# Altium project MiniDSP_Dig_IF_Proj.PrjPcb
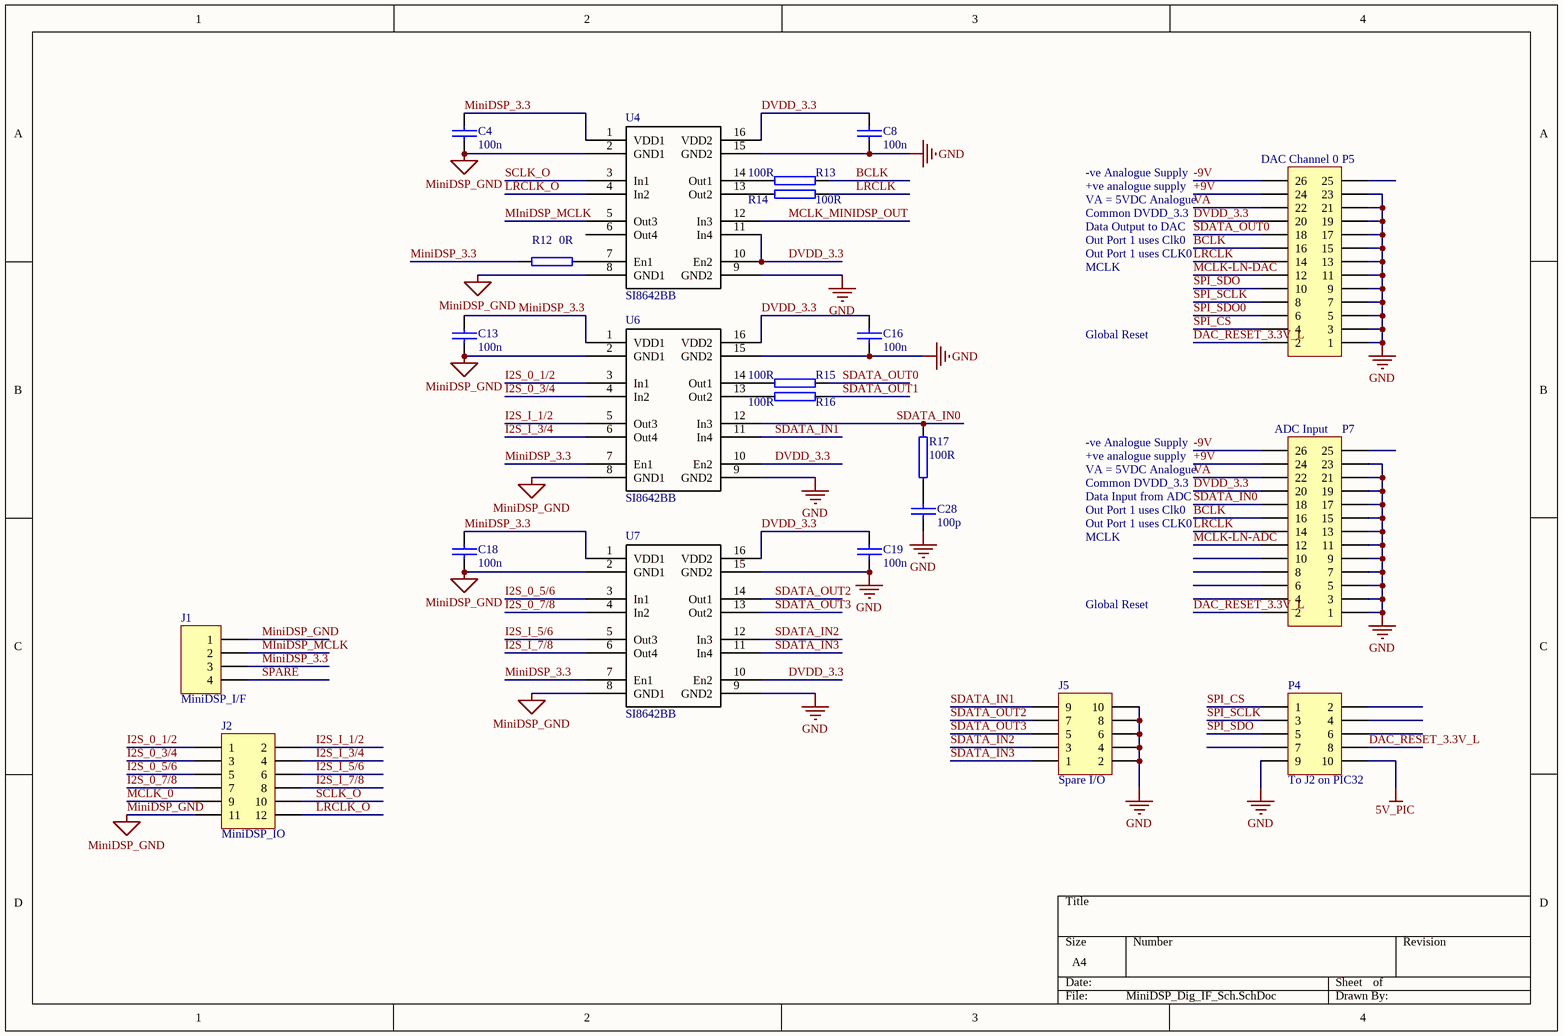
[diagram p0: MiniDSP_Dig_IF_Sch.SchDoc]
3 sheets, 95 parts. Net scope: global (net labels, ports and power ports of the same name join across sheets).
Board file: MiniDSP_Dig_IF_PCB.PcbDoc
Sheets:
  MiniDSP_Dig_IF_Sch.SchDoc
  MiniDSP_Dis_IF_PSU.SchDoc
  MiniDSP_DIG_Clk.SchDoc

## Sheet MiniDSP_Dig_IF_Sch.SchDoc
size A4

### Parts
C4  100n  [AXIAL0.2-pth]
C8  100n  [AXIAL0.2-pth]
C13  100n  [AXIAL0.2-pth]
C16  100n  [AXIAL0.2-pth]
C18  100n  [AXIAL0.2-pth]
C19  100n  [AXIAL0.2-pth]
C28  100p  [0805]
J1  MiniDSP_I/F  [HDR1X4]
J2  MiniDSP_IO  [HDR2X6]
J5  Spare I/O  [HDR2X5]
P4  To J2 on PIC32  [HDR2X5]
P5  DAC Channel 0  [HDR2X13]
P7  ADC Input  [HDR2X13]
R12  0R  [AXIAL0.4]
R13  100R  [0805]
R14  100R  [0805]
R15  100R  [0805]
R16  100R  [0805]
R17  100R  [0805]
U4  SI8642BB  [SOIC16-Wide]
U6  SI8642BB  [SOIC16-Wide]
U7  SI8642BB  [SOIC16-Wide]

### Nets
5V_PIC: P4.10
+9V: P5.24 P7.24
-9V: P5.26 P7.26
DVDD_3.3: C8.2 C16.2 C19.2 P5.20 P7.20 U4.10(En2) U4.11(In4) U4.16(VDD2) U6.10(En2) U6.16(VDD2) U7.10(En2) U7.16(VDD2)
GND: C8.1 C16.1 C19.1 C28.2 J5.2 J5.4 J5.6 J5.8 J5.10 P4.9 P5.1 P5.3 P5.5 P5.7 P5.9 P5.11 P5.13 P5.15 P5.17 P5.19 P5.21 P5.23 P7.1 P7.3 P7.5 P7.7 P7.9 P7.11 P7.13 P7.15 P7.17 P7.19 P7.21 P7.23 U4.9(GND2) U4.15(GND2) U6.9(GND2) U6.15(GND2) U7.9(GND2) U7.15(GND2)
MiniDSP_GND: C4.1 C13.1 C18.1 J1.1 J2.11 U4.2(GND1) U4.8(GND1) U6.2(GND1) U6.8(GND1) U7.2(GND1) U7.8(GND1)
VA: P5.22 P7.22
BCLK: P5.16 P7.16 R13.2
DAC_RESET_3.3V_L: P4.8 P5.2 P7.2
I2S_0_1/2: J2.1 U6.3(In1)
I2S_0_3/4: J2.3 U6.4(In2)
I2S_0_5/6: J2.5 U7.3(In1)
I2S_0_7/8: J2.7 U7.4(In2)
I2S_I_1/2: J2.2 U6.5(Out3)
I2S_I_3/4: J2.4 U6.6(Out4)
I2S_I_5/6: J2.6 U7.5(Out3)
I2S_I_7/8: J2.8 U7.6(Out4)
LRCLK: P5.14 P7.14 R14.2
LRCLK_O: J2.12 U4.4(In2)
MCLK-LN-ADC: P7.12
MCLK-LN-DAC: P5.12
MCLK_0: J2.9
MCLK_MINIDSP_OUT: U4.12(In3)
MiniDSP_3.3: C4.2 C13.2 C18.2 J1.3 R12.1 U4.1(VDD1) U6.1(VDD1) U6.7(En1) U7.1(VDD1) U7.7(En1)
MIniDSP_MCLK: J1.2 U4.5(Out3)
SCLK_O: J2.10 U4.3(In1)
SDATA_IN0: P7.18 R17.2 U6.12(In3)
SDATA_IN1: J5.9 U6.11(In4)
SDATA_IN2: J5.3 U7.12(In3)
SDATA_IN3: J5.1 U7.11(In4)
SDATA_OUT0: P5.18 R15.2
SDATA_OUT1: R16.2
SDATA_OUT2: J5.7 U7.14(Out1)
SDATA_OUT3: J5.5 U7.13(Out2)
SPARE: J1.4
SPI_CS: P4.1 P5.4
SPI_SCLK: P4.3 P5.8
SPI_SDO: P4.5 P5.10
SPI_SDO0: P5.6
NetC28_1: C28.1 R17.1
NetR12_2: R12.2 U4.7(En1)
NetR13_1: R13.1 U4.14(Out1)
NetR14_1: R14.1 U4.13(Out2)
NetR15_1: R15.1 U6.14(Out1)
NetR16_1: R16.1 U6.13(Out2)

Not connected (* = marked no-connect by the designer): P4 2 4 6 7; P5 25; P7 4 6 8 10 25; U4 6(Out4)

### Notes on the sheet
- -ve Analogue Supply
- VA = 5VDC Analogue
- +ve analogue supply
- Common DVDD_3.3
- Out Port 1 uses Clk0
- Data Output to DAC
- MCLK
- Out Port 1 uses CLK0
- Global Reset
- Data Input from ADC

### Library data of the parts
C4 C8 C13 C16 C18 C19 = CAP: Capacitor
C28 = CAP
J1 = Header 4: Header, 4-Pin
J2 = Header 6X2: Header, 6-Pin, Dual row
J5 P4 = Header 5X2: Header, 5-Pin, Dual row
P5 P7 = Header 13X2: Header, 13-Pin, Dual row
R12-R17 = RES2
U4 U6 U7 = SI8642BB: SILICON LABS DIGITAL ISOLATOR, 8NS, WSOIC-16, Element14 P/N 2423200

## Sheet MiniDSP_Dis_IF_PSU.SchDoc
size A4
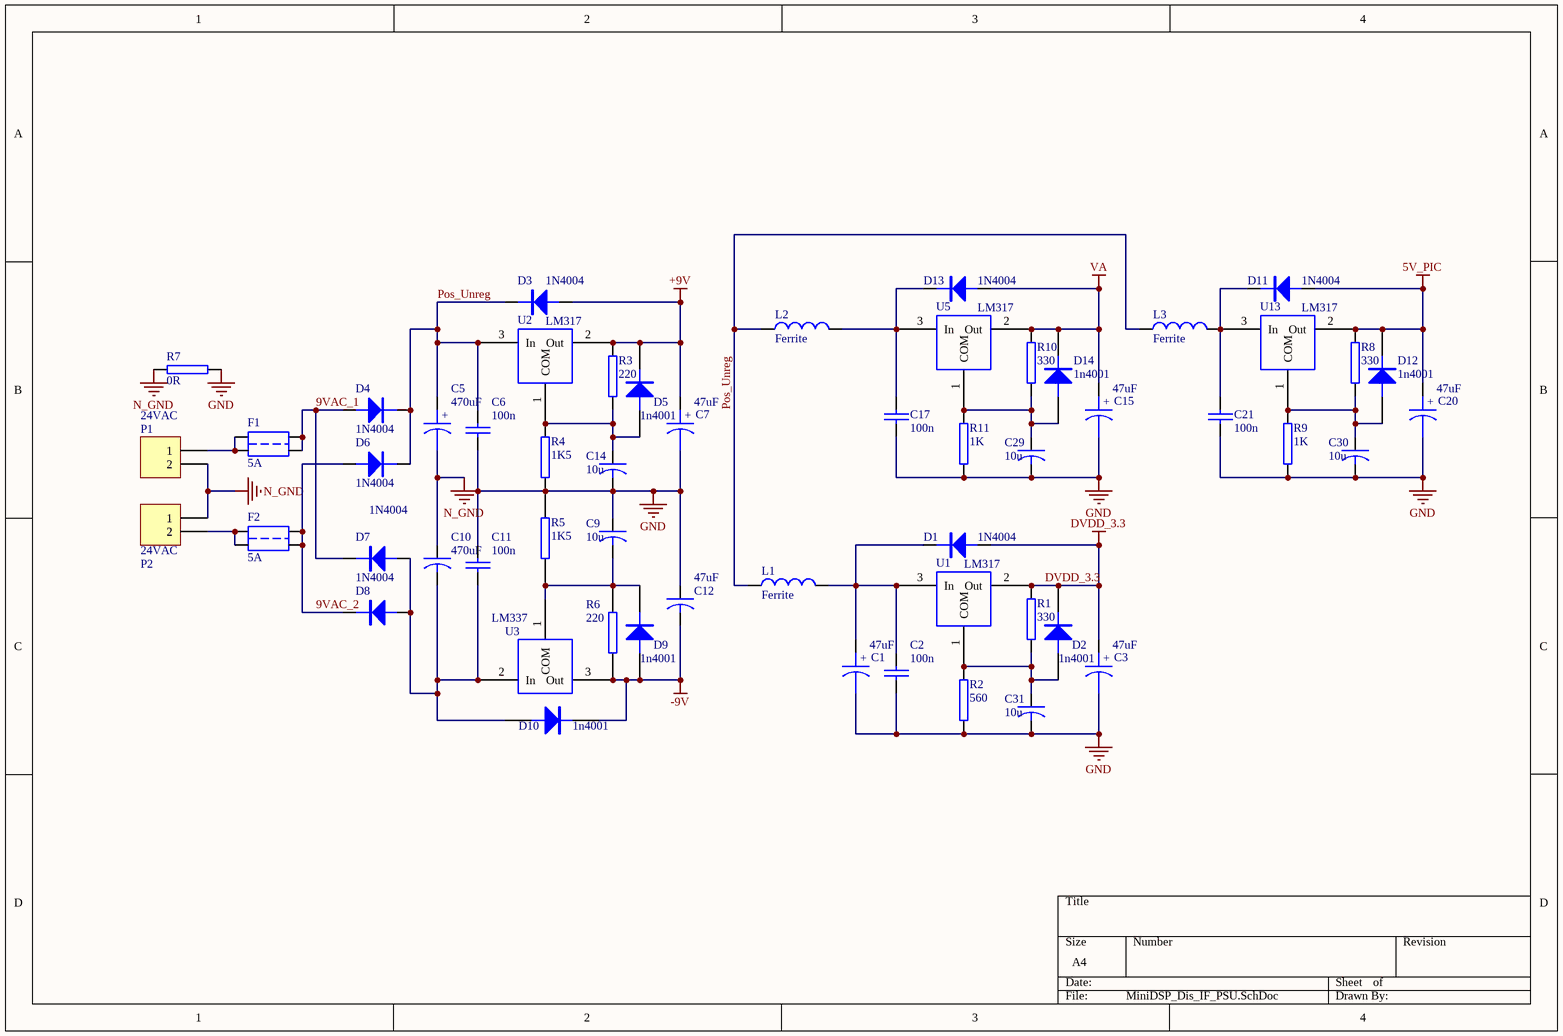
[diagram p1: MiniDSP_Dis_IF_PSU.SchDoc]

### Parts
C1  47uF  [RB.16/.32-PTH]
C2  100n  [AXIAL0.2-pth]
C3  47uF  [RB.16/.32-PTH]
C5  470uF  [RB.3/.6]
C6  100n  [AXIAL0.2-pth]
C7  47uF  [RB.16/.32-PTH]
C9  10u  [RB.1/.2-PTH]
C10  470uF  [RB.3/.6]
C11  100n  [AXIAL0.2-pth]
C12  47uF  [RB.16/.32-PTH]
C14  10u  [RB.1/.2-PTH]
C15  47uF  [RB.16/.32-PTH]
C17  100n  [AXIAL0.2-pth]
C20  47uF  [RB.16/.32-PTH]
C21  100n  [AXIAL0.2-pth]
C29  10u  [RB.1/.2-PTH]
C30  10u  [RB.1/.2-PTH]
C31  10u  [RB.1/.2-PTH]
D1  1N4004  [DIODE0.35-TH]
D2  1n4001  [DIODE0.35-pth]
D3  1N4004  [DIODE0.35-TH]
D4  1N4004  [DIODE0.35-TH]
D5  1n4001  [DIODE0.35-pth]
D6  1N4004  [DIODE0.35-TH]
D7  1N4004  [DIODE0.35-TH]
D8  1N4004  [DIODE0.35-TH]
D9  1n4001  [DIODE0.35-pth]
D10  1n4001  [DIODE0.35-pth]
D11  1N4004  [DIODE0.35-TH]
D12  1n4001  [DIODE0.35-pth]
D13  1N4004  [DIODE0.35-TH]
D14  1n4001  [DIODE0.35-pth]
F1  5A  [FUSE-Small-M205]
F2  5A  [FUSE-Small-M205]
L1  Ferrite  [AXIAL0.4]
L2  Ferrite  [AXIAL0.4]
L3  Ferrite  [AXIAL0.4]
P1  24VAC  [CON2_SCREW]
P2  24VAC  [CON2_SCREW]
R1  330  [AXIAL0.4]
R2  560  [AXIAL0.4]
R3  220  [AXIAL0.4]
R4  1K5  [AXIAL0.4]
R5  1K5  [AXIAL0.4-pth]
R6  220  [AXIAL0.4-pth]
R7  0R  [AXIAL0.4]
R8  330  [AXIAL0.4]
R9  1K  [AXIAL0.4]
R10  330  [AXIAL0.4]
R11  1K  [AXIAL0.4]
U1  LM317  [TO-220-REG]
U2  LM317  [TO-220-REG]
U3  LM337  [TO-220-REG]
U5  LM317  [TO-220-REG]
U13  LM317  [TO-220-REG]

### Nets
5V_PIC: C20.1 D11.1(A) D12.2(K) R8.2 U13.2(Out)
+9V: C7.1 D3.1(A) D5.2(K) R3.2 U2.2(Out)
-9V: C12.2 D9.1(A) D10.2(K) R6.1 U3.3(Out)
DVDD_3.3: C3.1 D1.1(A) D2.2(K) R1.2 U1.2(Out)
GND: C1.2 C2.2 C3.2 C6.2 C7.2 C9.1 C11.1 C12.1 C14.2 C15.2 C17.2 C20.2 C21.2 C29.2 C30.2 C31.2 R2.1 R4.1 R5.2 R7.1 R9.1 R11.1
N_GND: C5.2 C10.1 P1.2 P2.1 R7.2
VA: C15.1 D13.1(A) D14.2(K) R10.2 U5.2(Out)
9VAC_1: D4.1(A) D7.2(K) F1.2 F1.4
9VAC_2: D6.1(A) D8.2(K) F2.2 F2.4
Pos_Unreg: C5.1 C6.1 D3.2(K) D4.2(K) D6.2(K) L1.1 L2.1 L3.1 U2.3(In)
NetC1_1: C1.1 C2.1 D1.2(K) L1.2 U1.3(In)
NetC9_2: C9.2 D9.2(K) R5.1 R6.2 U3.1(COM)
NetC10_2: C10.2 C11.2 D7.1(A) D8.1(A) D10.1(A) U3.2(In)
NetC14_1: C14.1 D5.1(A) R3.1 R4.2 U2.1(COM)
NetC17_1: C17.1 D13.2(K) L2.2 U5.3(In)
NetC21_1: C21.1 D11.2(K) L3.2 U13.3(In)
NetC29_1: C29.1 D14.1(A) R10.1 R11.2 U5.1(COM)
NetC30_1: C30.1 D12.1(A) R8.1 R9.2 U13.1(COM)
NetC31_1: C31.1 D2.1(A) R1.1 R2.2 U1.1(COM)
NetF1_1: F1.1 F1.3 P1.1
NetF2_1: F2.1 F2.3 P2.2

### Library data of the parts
C1 C3 C5 C7 C15 C20 = CAPACITOR POL
C2 C6 C11 C17 C21 = CAP: Capacitor
C9 C10 C12 C14 C29-C31 = CAPACITOR
D1 D3 D4 D6-D8 D11 D13 = DIODE_Numbered
D2 D5 D9 D10 D12 D14 = DIODE
F1 F2 = FUSE1
L1-L3 = Inductor: Code_IEC: 1005
P1 P2 = Header 2: Header, 2-Pin
R1-R11 = RES2

## Sheet MiniDSP_DIG_Clk.SchDoc
size A4
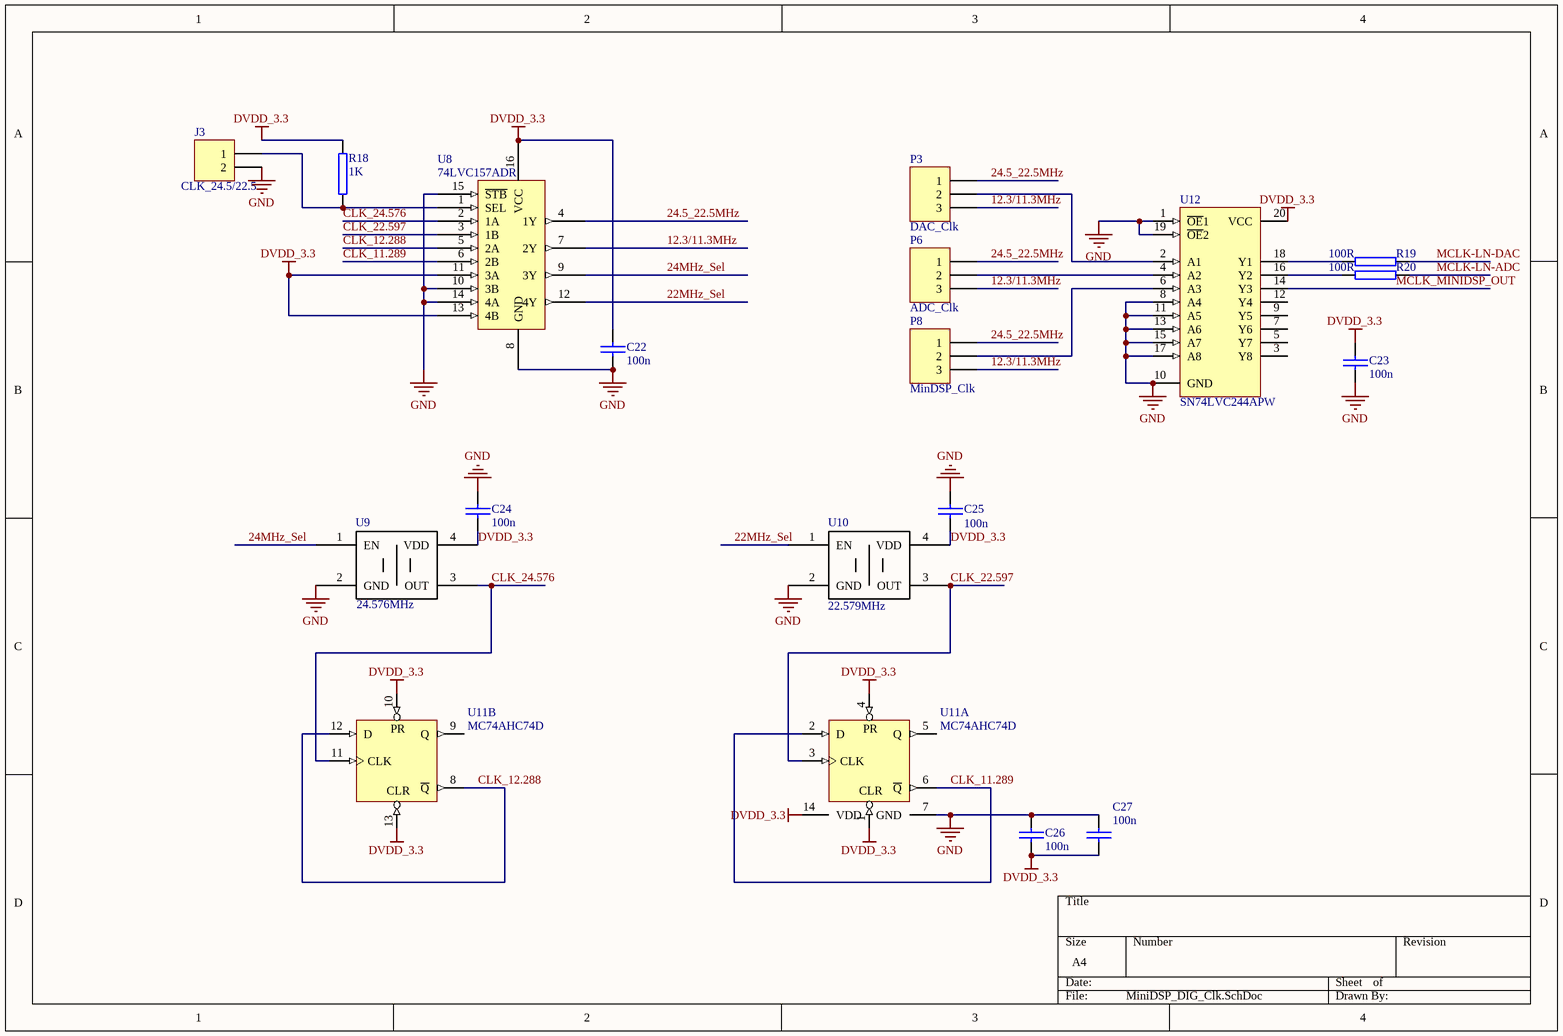
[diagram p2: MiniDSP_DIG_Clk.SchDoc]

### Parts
C22  100n  [0805]
C23  100n  [0805]
C24  100n  [0805]
C25  100n  [0805]
C26  100n  [0805]
C27  100n  [AXIAL0.2-pth]
J3  CLK_24.5/22.5  [HDR1X2]
P3  DAC_Clk  [HDR1X3]
P6  ADC_Clk  [HDR1X3]
P8  MinDSP_Clk  [HDR1X3]
R18  1K  [0805]
R19  100R  [0805]
R20  100R  [0805]
U8  74LVC157ADR  [D016_N]
U9  24.576MHz  [SMD_XCO]
U10  22.579MHz  [SMD_XCO]
U11  MC74AHC74D  [751A-03_N]  (parts A,B of 2)
U12  SN74LVC244APW  [PW020_N]

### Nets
DVDD_3.3: C22.2 C23.2 C24.2 C25.2 C26.2 C27.2 R18.2 U8.11(3A) U8.13(4B) U8.16(VCC) U9.4(VDD) U10.4(VDD) U11.1(CLR) U11.4(PR) U11.10(PR) U11.13(CLR) U11.14(VDD) U12.20(VCC)  [also labelled VCC, VDD]
GND: C22.1 C23.1 C24.1 C25.1 C26.1 C27.1 J3.2 U8.8(GND) U8.10(3B) U8.14(4A) U8.15(~{STB}) U9.2(GND) U10.2(GND) U11.7(GND) U12.1(~{OE}1) U12.8(A4) U12.10(GND) U12.11(A5) U12.13(A6) U12.15(A7) U12.17(A8) U12.19(~{OE}2)
12.3/11.3MHz: P3.3 P6.3 P8.3 U8.7(2Y)
22MHz_Sel: U8.12(4Y) U10.1(EN)
24.5_22.5MHz: P3.1 P6.1 P8.1 U8.4(1Y)
24MHz_Sel: U8.9(3Y) U9.1(EN)
CLK_11.289: U8.6(2B) U11.2(D) U11.6(~{Q})
CLK_12.288: U8.5(2A) U11.8(~{Q}) U11.12(D)
CLK_22.597: U8.3(1B) U10.3(OUT) U11.3(CLK)
CLK_24.576: U8.2(1A) U9.3(OUT) U11.11(CLK)
MCLK-LN-ADC: R20.2
MCLK-LN-DAC: R19.2
MCLK_MINIDSP_OUT: U12.14(Y3)
NetJ3_1: J3.1 R18.1 U8.1(SEL)
NetP3_2: P3.2 U12.2(A1)
NetP6_2: P6.2 U12.4(A2)
NetP8_2: P8.2 U12.6(A3)
NetR19_1: R19.1 U12.18(Y1)
NetR20_1: R20.1 U12.16(Y2)

Not connected (* = marked no-connect by the designer): U11 5(Q) 9(Q); U12 3(Y8) 5(Y7) 7(Y6) 9(Y5) 12(Y4)

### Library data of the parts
C22-C26 = CAP
C27 = CAP: Capacitor
J3 = Header 2: Header, 2-Pin
P3 P6 P8 = Header 3: Header, 3-Pin
R18-R20 = RES2
U8 = 74LVQ157M(16): Low Voltage Quad 2 Channel Multiplexer, Eleement14 P/N: 1236314
U9 = XCO: Xtal Oscllator Module, Element14 P/N: 1842177
U10 = XCO: Xtal Oscllator Module, Element14 P/N: 2405758
U11 = MC74AC74D: Dual D-Type Positive Edge-Triggered Flip-Flop, , Element14 P/N 1749933
U12 = SN74LVC244APW: Octal Buffer/Driver with 3-State Outputs

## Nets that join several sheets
5V_PIC: MiniDSP_Dig_IF_Sch (P4.10), MiniDSP_Dis_IF_PSU (5 pins)
+9V: MiniDSP_Dig_IF_Sch (P5.24 P7.24), MiniDSP_Dis_IF_PSU (5 pins)
-9V: MiniDSP_Dig_IF_Sch (P5.26 P7.26), MiniDSP_Dis_IF_PSU (5 pins)
DVDD_3.3: MiniDSP_Dig_IF_Sch (12 pins), MiniDSP_Dis_IF_PSU (5 pins), MiniDSP_DIG_Clk (18 pins)
GND: MiniDSP_Dig_IF_Sch (40 pins), MiniDSP_Dis_IF_PSU (22 pins), MiniDSP_DIG_Clk (22 pins)
VA: MiniDSP_Dig_IF_Sch (P5.22 P7.22), MiniDSP_Dis_IF_PSU (5 pins)
MCLK-LN-ADC: MiniDSP_Dig_IF_Sch (P7.12), MiniDSP_DIG_Clk (R20.2)
MCLK-LN-DAC: MiniDSP_Dig_IF_Sch (P5.12), MiniDSP_DIG_Clk (R19.2)
MCLK_MINIDSP_OUT: MiniDSP_Dig_IF_Sch (U4.12), MiniDSP_DIG_Clk (U12.14)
